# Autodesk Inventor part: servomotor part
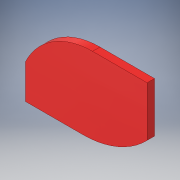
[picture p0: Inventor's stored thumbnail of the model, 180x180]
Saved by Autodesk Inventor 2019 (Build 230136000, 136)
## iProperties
Created: 2021-07
Part Number: servomotor part
Material: Generic
Document SubType Name: Modeling
Designer: Avinash
Density: 1 g/cm^3
Appearance: Light Red
Author: Avinash
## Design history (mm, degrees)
sketch "Sketch2"
  geometry: L1 (0, 0)-(-69.384, 0); L2 (-101.444, 16.55)-(-101.444, 90); L3 (-101.444, 90)-(0, 90); L4 (0, 90)-(0, 0); L5 (-69.384, 0)-(-130.689, 0); L6 (-130.689, 0)-(-130.689, 16.55); L7 (-130.689, 16.55)-(-101.444, 16.55); C1 r 3.5 at (-118.93, 8.275)
  constraints: 14 end point, 3 parallel, 2 horizontal, 2 perpendicular, 1 centre point
  dimensions: "d2" = 90 distance of L3.end L1.start; "d3" = 16.55 distance of L5.end L6.end; "d4" = 7 diameter of C1
extrude "Extrusion1" new body sketch "Sketch2" distance "d5" = 5; taper "d6" = 0 deg
fillet "Fillet2" dims "d8" = 60
sketch "Sketch3"
  geometry: L1 (-0.402, 51.909)-(101.444, 51.909); L2 (101.444, 16.55)-(101.444, 90) reference; L3 (-0.402, 51.909)-(101.444, 51.909); L4 (101.444, 51.909)-(101.444, 105.031); L5 (101.444, 105.031)-(-0.402, 105.031); L6 (-0.402, 105.031)-(-0.402, 51.909); 1 further point
  constraints: 10 end point, 2 horizontal, 2 parallel, 1 perpendicular, 1 point on line
extrude "Extrusion2" cut sketch "Sketch3" distance "d9" = 10; taper "d10" = 0 deg
sketch "Sketch4"
  geometry: L1 (16.884, 18.275)-(16.884, 51.909); L2 (16.884, 18.275)-(-7.685, 18.275); L3 (-7.685, 18.275)-(-7.685, 51.909); L4 (-7.685, 51.909)-(16.884, 51.909); L5 (16.884, 51.909)-(16.884, 18.275); A1 r 60 centre (60, 60) between (0.548, 51.909) and (60, 0) reference; 1 further point
  constraints: 10 end point, 2 parallel, 1 horizontal, 1 perpendicular, 1 point on circle, 1 vertical
extrude "Extrusion3" cut sketch "Sketch4" distance "d11" = 10; taper "d12" = 0 deg
fillet "Fillet3" dims "d13" = 50
sketch "Sketch5"
  geometry: L1 (-147.382, 36.06)-(-98.837, 36.06); L2 (-98.837, 36.06)-(-98.837, -18.423); L3 (-98.837, -18.423)-(-147.382, -18.423); L4 (-147.382, -18.423)-(-147.382, 36.06); 1 further point
  constraints: 8 end point, 2 parallel, 1 horizontal, 1 perpendicular
extrude "Extrusion4" cut sketch "Sketch5" distance "d14" = 10; taper "d15" = 0 deg
body "Solid1"
